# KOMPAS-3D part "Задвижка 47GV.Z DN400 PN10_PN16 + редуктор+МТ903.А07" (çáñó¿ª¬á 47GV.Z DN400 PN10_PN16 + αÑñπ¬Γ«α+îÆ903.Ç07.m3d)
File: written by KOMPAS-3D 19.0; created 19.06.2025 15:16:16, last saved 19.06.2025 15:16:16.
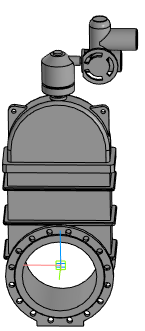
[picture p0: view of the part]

Document properties: Полное имя файла: Задвижка 47GV.Z DN400 PN10_PN16 + редуктор+МТ903.А07.a3d

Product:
- Part/product: Задвижка 47GV.Z DN400 PN10_PN16 + редуктор+МТ903.А07
    Масса: 845.528

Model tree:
1. Операция без истории:1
